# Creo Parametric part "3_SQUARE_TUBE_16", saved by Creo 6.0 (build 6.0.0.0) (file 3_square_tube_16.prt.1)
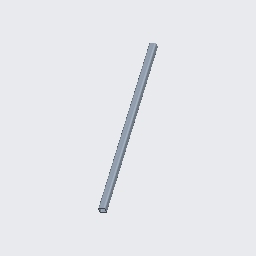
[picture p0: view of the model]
Units: Custom; MM, KILOGRAM, SECS
Materials in the file: STEEL

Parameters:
  BUW_NAME = "SQUARE TUBE"
  BUW_TYPE = "DIN EN 10219"
  BUW_SIZE = "25x25x3.0"
  BUW_LENGTH_STR = "680"
  PTC_MATERIAL_NAME = "STEEL"
  BUW_PROFIL_TYPE = "square_tube"
  BUW_PROFILE_PATH = "parts//profiles/steel_beams_mm/"
  BUW_PROFILE_NAME_LANG = "SQUARE TUBE"
  BUW_TAB_SEL_INFO = "-2 TYPE DIN_EN_10219-1997 SIZE_DINEN_10219 25x25x3.0"
  NAMING = "SQUARE TUBE"
  DESIGNATION = "DIN EN 10219 25x25x3.0 x 680"
  PROFIL_RASTER_POS = "X_0"
  BUW_OBJECT_ROLE = "PROFIL_SYSTEM_BORE_END_POINTS"
  PRO_UNIT_SYS = "Custom"

Other parameters: BUW_LENGTH, LENGTH, BUW_LENGTH_Z_MIN_PARAM, D8, D93, D94, d26, d8, d93, d94, d98, D98, SHEAR_MODULUS, THERM_EXPANSION_REF_TEMPERATURE, STRUCTURAL_DAMPING_COEFFICIENT, STRESS_LIMIT_FOR_TENSION, STRESS_LIMIT_FOR_COMPRESSION, STRESS_LIMIT_FOR_SHEAR, EMISSIVITY

Created from: SQUARE_TUBE.PRT

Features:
  1. datum plane "YZ"
  2. datum plane "XZ"
  3. datum plane "XY"
  4. coordinate system
  5. coordinate system
  6. coordinate system
  7. coordinate system
  8. datum plane "DTM3"
  9. datum plane "DTM4"
  10. datum plane "DTM5"
  11. protrusion
  12. round
  13. round
  14. datum axis
  15. datum point "PNT0"
  16. datum point

Other named items: PROFIL_CUT_QUILT, PROFILE_LENGTH_DIM, CONTACT_SURF_3, CONTACT_SURF_2, CONTACT_SURF_1, CONTACT_SURF_0, E, START_SURFACE, END_SURFACE, SIDE_SURF_3, SIDE_SURF_0, SIDE_SURF_1, SIDE_SURF_2, EDGE_7_S, EDGE_7_E, EDGE_1_S, EDGE_1_E, EDGE_3_S, EDGE_3_E, EDGE_5_S, EDGE_5_E, EDGE_6_S, EDGE_4_S, EDGE_2_S, EDGE_0_S, EDGE_6_E, EDGE_4_E, EDGE_2_E, EDGE_0_E, CS0, CS_S, CS_E, CS3

Named dimensions: X_ROT_S, Y_ROT_S, Z_OFF_S, X_ROT_E, Y_ROT_E, Z_OFF_E, PC_L, BUW_LENGTH_Z_MIN, BUW_LENGTH_DIM

Layers: 00_PROFIL_DATUM, 00_PROFIL_DRW_HIDE, 00_PROFIL_END_CSYS, 00_PROFIL_GEOMETRY, 00_PROFIL_QUILT, 00_PROFIL_SIZE_NOTE

Surfaces: 16 plane, 12 cylinder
